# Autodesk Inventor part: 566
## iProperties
Author: Administrator
Shininess: 64.0
Angle Display Precision: 2
Document Length Units: 11272
Document Angle Units: 11286
Document Time Units: 11279
Document Mass Units: 11290
Document Length Units Precision: 3
Document Angle Units Precision: 2
Compacted: True
PropertySet Name: _Private Model Information
Created: 2002-03
Part Number: 566
Material: Stainless Steel, 440C
Document SubType Name: Modeling
Designer: Administrator
Control State: 0
Master: False
Checked Out: False
PropertySet Name: Design Tracking Control
Density: 0.0
Volumn: 0.0
Area: 0.0
PropertySet Name: Model Information
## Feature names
1. Revolution1
